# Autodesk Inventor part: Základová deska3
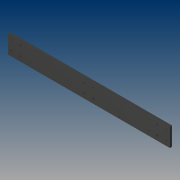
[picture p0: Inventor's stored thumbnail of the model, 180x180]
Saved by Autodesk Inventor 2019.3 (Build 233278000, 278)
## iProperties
Created: 2019-03
Part Number: Základová deska3
Material: Ocel, měkká, svařovaná
Document SubType Name: Modeling
Designer: B-hon
Density: 7.85 g/cm^3
Appearance: Jemná textura – černá
Author: B-hon
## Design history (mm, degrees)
sketch "Náčrt1"
  geometry: L1 (0, 0)-(1235, 0); L2 (1235, 0)-(1235, 140); L3 (1235, 140)-(0, 140); L4 (0, 140)-(0, 0)
  constraints: 8 end point, 2 parallel, 1 horizontal, 1 perpendicular
  dimensions: "d0" = 1235 distance of L3.end L2.end; "d1" = 140 distance of L2.end L1.end
extrude "Vysunutí1" new body sketch "Náčrt1" distance "d2" = 15; taper "d3" = 0 deg
sketch "Náčrt2"
  geometry: L1 (173, 109)-(1073, 109); L2 (1073, 109)-(1073, 31); L3 (1073, 31)-(173, 31); L4 (173, 31)-(173, 109); L5 (0, 0)-(1235, 0) reference; L6 (1235, 140)-(0, 140) reference; L7 (0, 140)-(0, 0) reference; 4 further points
  constraints: 8 end point, 4 coincident, 2 parallel, 1 horizontal, 1 perpendicular
  dimensions: "d4" = 900 distance of L2.end L3.end; "d5" = 78 distance of L1.end L2.end; "d6" = 140 distance between parallel lines of L5 L6 (derived); "d7" = 31 distance between parallel lines of L1 L6 (= -0.5 x d5 + 0.5 x d6); "d8" = 1235 distance of L6.start L6.end (derived); "d9" = 173 distance between parallel lines of L7 L4
hole "Díra1" sketch "Náčrt2" at (173, 109), (173, 31), (1073, 31), (1073, 109) diameter "d10" = 6.5; stored, may be unused: countersink angle "d14" = 90 deg, drill point angle "d16" = 0 deg; dims "d11" = 13, "d12" = 6, "d13" = 2, "d15" = 14.7
sketch "Náčrt3" dims "d17" = 100
  geometry: L1 (1235, 140)-(0, 140) reference; L2 (0, 140)-(0, 0) reference; L3 (60, 70)-(154.986, 70); 1 further point
  constraints: 2 end point, 1 horizontal, 3 other
  dimensions: "d18" = 70 distance from line of L1 L3.start; "d19" = 60 distance from line of L2 L3.start; "d52" = 45 deg dimension on L3.start point (95.355, 105.355) L3.end
hole "Díra2" sketch "Náčrt3" at (95.355, 105.355) diameter "d20" = 10.5; stored, may be unused: countersink angle "d24" = 90 deg, drill point angle "d26" = 0 deg; dims "d21" = 20, "d22" = 6, "d23" = 2, "d25" = 27.3
sketch "Náčrt4"
  geometry: L1 (60, 70)-(178.058, 70); C1 r 5.25 at (95.355, 105.355) reference; 1 further point
  constraints: 2 end point, 1 horizontal
  dimensions: "d53" = 45 deg dimension on L1.start C1.centre L1.end; "d54" = 50 distance of C1.centre L1.start
hole "Díra5" sketch "Náčrt4" diameter "d55" = 4.5; stored, may be unused: countersink angle "d59" = 90 deg, drill point angle "d61" = 118 deg; dims "d56" = 6, "d57" = 4, "d58" = 2, "d60" = 8
pattern_circular "Kruhové pole2" dims angle "d63" = 360 deg
pattern_linear "Obdélníkové pole2" dims "d67" = 557.5
sketch "Náčrt7"
  geometry: L1 (1235, 0)-(1235, 140) reference; L2 (0, 0)-(1235, 0) reference; 2 further points
  constraints: 1 vertical alignment
  dimensions: "d81" = 385 distance from line of L1 point (850, 11); "d82" = 11 distance from line of L2 point (850, 11); "d83" = 48 distance of point (850, 11) point (850, 59)
hole "Díra7" sketch "Náčrt7" at (850, 11), (850, 59) diameter "d84" = 6.4; stored, may be unused: countersink angle "d88" = 90 deg, drill point angle "d90" = 118 deg; dims "d85" = 8, "d86" = 4, "d87" = 2, "d89" = 12
node "Těleso1"
